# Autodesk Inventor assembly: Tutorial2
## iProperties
Created: 2004-07
Part Number: Tutorial2
Document SubType Name: Weldment
Designer: CADCIM Technologies
Manufacturer: Standard
Standards Organization: Custom
Author: CADCIM Technologies
